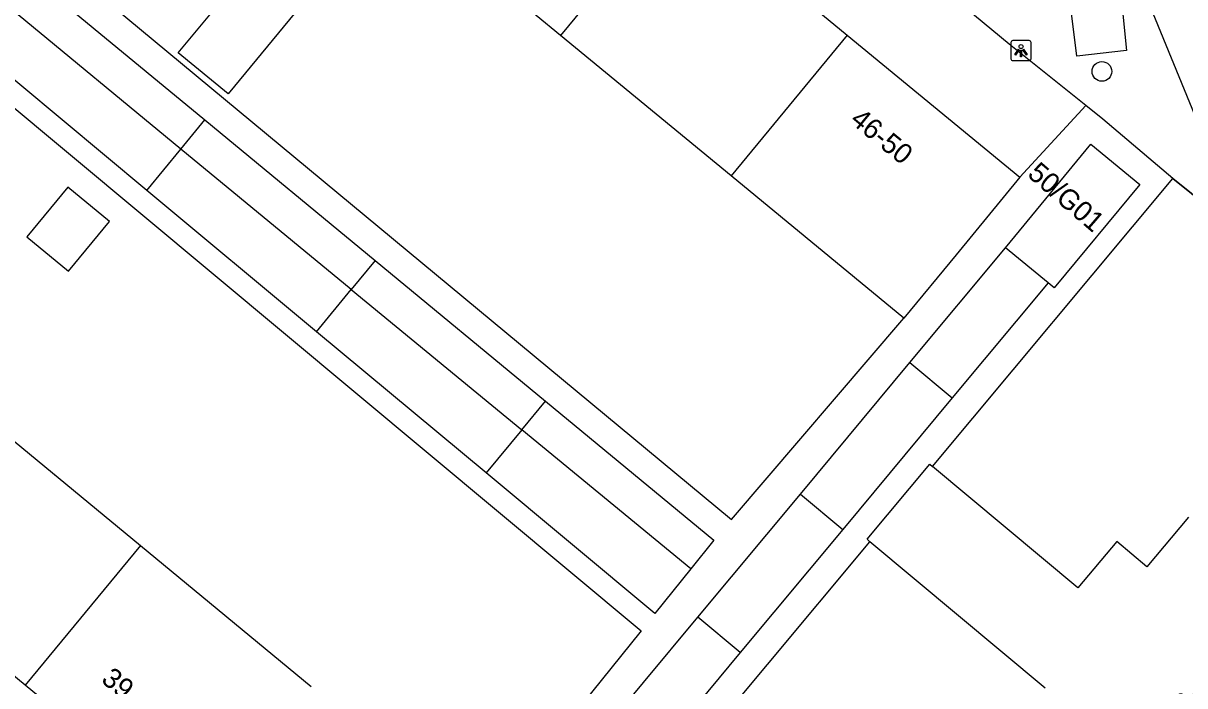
# Model space of a CAD drawing. Extents: x 162074 to 163034, y 381824 to 382557.
# Drawn here: x 162389.4 to 162447.1, y 382037.4 to 382070.3 of the extents above; entities that cross this region are included whole.
import ezdxf

# ---------------------------------------------------------------- set-up
doc = ezdxf.new("R2010")
doc.units = 0
for name, color, linetype in [('IMGEO_Boom', 7, 'Continuous'), ('IMGEO_Lichtpunt', 7, 'Continuous'), ('IMGEO_Muur', 7, 'Continuous'), ('IMGEO_Pand', 7, 'Continuous'), ('IMGEO_Pand_nummerreeks', 7, 'Continuous'), ('IMGEO_Rijbaan_lokaal_open', 7, 'Continuous'), ('IMGEO_Voetpad_open', 7, 'Continuous')]:
    doc.layers.add(name, color=color, linetype=linetype)

msp = doc.modelspace()

# ---------------------------------------------------------------- linework, layer by layer
at = {"layer": 'IMGEO_Boom'}
msp.add_circle((162443, 382067.946), 0.489, dxfattribs=at)
at = {"layer": 'IMGEO_Lichtpunt'}
for p, q in [((162439.384, 382069.479), (162438.576, 382069.479)), ((162439.384, 382069.479), (162438.576, 382069.479)), ((162438.482, 382069.384), (162438.482, 382068.577)), ((162438.482, 382069.384), (162438.482, 382068.577)), ((162439.478, 382068.577), (162439.478, 382069.384)), ((162439.478, 382068.577), (162439.478, 382069.384)), ((162438.576, 382068.483), (162439.384, 382068.483)), ((162438.576, 382068.483), (162439.384, 382068.483))]:
    msp.add_line(p, q, dxfattribs=at)
for points in [[(162438.856, 382069.048), (162438.895, 382069.02), (162438.707, 382068.758), (162438.669, 382068.785), (162438.856, 382069.048)], [(162438.958, 382069), (162439.005, 382069), (162439.005, 382068.678), (162438.958, 382068.678), (162438.958, 382069)], [(162439.068, 382069.02), (162439.106, 382069.047), (162439.293, 382068.785), (162439.254, 382068.757), (162439.068, 382069.02)]]:
    msp.add_lwpolyline(points, dxfattribs=at)
msp.add_circle((162438.981, 382069.182), 0.0994, dxfattribs=at)
for centre, start, end in [((162438.576, 382069.384), 90, 180), ((162438.576, 382069.384), 90, 180), ((162439.384, 382069.384), 0, 90), ((162439.384, 382069.384), 0, 90), ((162438.576, 382068.577), 180, 270), ((162438.576, 382068.577), 180, 270), ((162439.384, 382068.577), 270, 0), ((162439.384, 382068.577), 270, 360)]:
    msp.add_arc(centre, 0.0946, start, end, dxfattribs=at)
at = {"layer": 'IMGEO_Muur'}
msp.add_lwpolyline([(162454.536, 382056.174), (162446.525, 382062.616)], dxfattribs=at)
at = {"layer": 'IMGEO_Pand'}
for points in [[(162407.629, 382076.713), (162406.717, 382077.465), (162405.257, 382075.693), (162406.221, 382074.898), (162399.57, 382066.827), (162397.097, 382068.865), (162398.824, 382070.962), (162397.342, 382072.183), (162401.766, 382077.552), (162397.197, 382081.316), (162399.157, 382083.694)], [(162416.1, 382069.733), (162407.629, 382076.713)], [(162421.871, 382076.736), (162416.1, 382069.733)], [(162421.871, 382076.736), (162430.342, 382069.755)], [(162389.955, 382072.525), (162398.418, 382065.534)], [(162397.225, 382064.085), (162388.753, 382071.067)], [(162424.572, 382062.752), (162416.1, 382069.733)], [(162430.342, 382069.755), (162424.572, 382062.752)], [(162430.342, 382069.755), (162438.929, 382062.68)], [(162395.528, 382062.026), (162387.093, 382069.052)], [(162397.225, 382064.085), (162398.418, 382065.534)], [(162398.418, 382065.534), (162406.881, 382058.544)], [(162438.206, 382059.176), (162442.45, 382064.327), (162444.879, 382062.326), (162440.635, 382057.175), (162440.325, 382057.43)], [(162395.528, 382062.026), (162397.225, 382064.085)], [(162405.695, 382057.105), (162397.225, 382064.085)], [(162433.159, 382055.677), (162424.572, 382062.752)], [(162438.929, 382062.68), (162435.75, 382058.822), (162433.159, 382055.677)], [(162393.681, 382060.479), (162391.612, 382062.187), (162389.571, 382059.714), (162391.639, 382058.007), (162393.681, 382060.479)], [(162403.962, 382055.001), (162395.528, 382062.026)], [(162433.451, 382053.462), (162438.206, 382059.176)], [(162440.325, 382057.43), (162438.206, 382059.176)], [(162406.881, 382058.544), (162405.695, 382057.105)], [(162406.881, 382058.544), (162415.345, 382051.553)], [(162440.325, 382057.43), (162435.561, 382051.705)], [(162403.962, 382055.001), (162405.695, 382057.105)], [(162405.695, 382057.105), (162414.167, 382050.123)], [(162412.397, 382047.975), (162403.962, 382055.001)], [(162428.013, 382046.927), (162433.451, 382053.462)], [(162433.451, 382053.462), (162435.561, 382051.705)], [(162414.167, 382050.123), (162415.345, 382051.553)], [(162415.345, 382051.553), (162423.719, 382044.636), (162422.567, 382043.201)], [(162435.561, 382051.705), (162430.124, 382045.17)], [(162386.731, 382051.368), (162395.214, 382044.365)], [(162414.167, 382050.123), (162412.397, 382047.975)], [(162422.567, 382043.201), (162414.167, 382050.123)], [(162431.473, 382044.558), (162431.329, 382044.679), (162434.446, 382048.406), (162434.583, 382048.291)], [(162447.3, 382045.77), (162445.238, 382043.312), (162443.737, 382044.571), (162441.797, 382042.258), (162434.583, 382048.291)], [(162422.567, 382043.201), (162420.788, 382040.985), (162412.397, 382047.975)], [(162422.917, 382040.802), (162428.013, 382046.927)], [(162428.013, 382046.927), (162430.124, 382045.17)], [(162430.124, 382045.17), (162425.028, 382039.045)], [(162389.484, 382037.423), (162381.001, 382044.426)], [(162395.214, 382044.365), (162389.484, 382037.423)], [(162395.214, 382044.365), (162403.697, 382037.363)], [(162440.187, 382037.271), (162431.473, 382044.558)], [(162417.517, 382034.312), (162422.917, 382040.802)], [(162425.028, 382039.045), (162422.917, 382040.802)], [(162425.028, 382039.045), (162419.629, 382032.555)], [(162397.967, 382030.421), (162389.484, 382037.423)]]:
    msp.add_lwpolyline(points, dxfattribs=at)
at = {"layer": 'IMGEO_Rijbaan_lokaal_open'}
msp.add_lwpolyline([(162449.709, 382064.013), (162447.637, 382065.739), (162445.4, 382071.193), (162443.882, 382072.46)], dxfattribs=at)
at = {"layer": 'IMGEO_Voetpad_open'}
for points in [[(162442.197, 382066.248), (162438.394, 382069.293), (162374.058, 382122.534)], [(162344.316, 382086.382), (162352.681, 382096.404), (162420.1, 382040.13), (162412.215, 382030.331)], [(162367.87, 382092.748), (162424.591, 382045.656), (162433.159, 382055.677)], [(162443.882, 382072.46), (162444.221, 382068.98), (162441.755, 382068.708), (162441.451, 382071.1)], [(162438.929, 382062.68), (162442.197, 382066.248)], [(162446.525, 382062.616), (162443.042, 382065.571), (162442.197, 382066.248)], [(162434.583, 382048.291), (162446.525, 382062.616)], [(162446.525, 382062.616), (162454.536, 382056.174)], [(162411.121, 382020.146), (162431.473, 382044.558)]]:
    msp.add_lwpolyline(points, dxfattribs=at)

# ---------------------------------------------------------------- texts
at = {"layer": 'IMGEO_Pand_nummerreeks'}
for s, rotation, p in [('46-50', 320.5113, (162430.433, 382065.43)), ('50/G01', 319.18249, (162439.248, 382062.76)), ('38-42', 50.00776, (162446.755, 382035.393)), ('39-43', 320.46014, (162393.212, 382037.613))]:
    msp.add_text(s, height=1, rotation=rotation, dxfattribs=at).set_placement(p)

doc.saveas('drawing.dxf')
